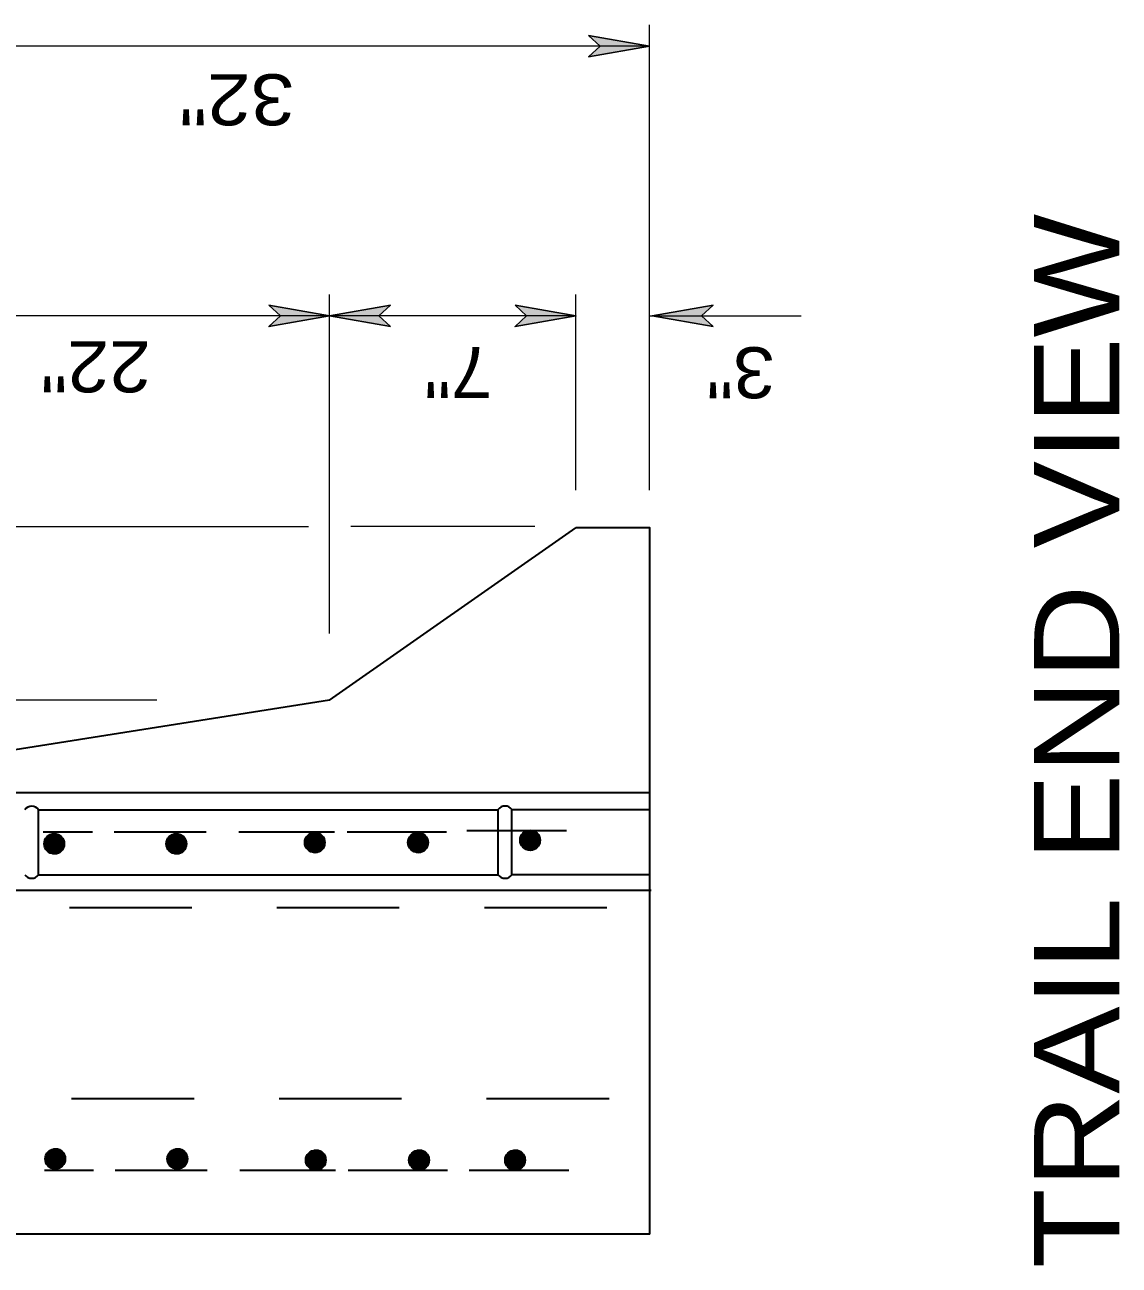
# Model space of a CAD drawing. Extents: x 12.6 to 19.5, y 6.1 to 16.3.
# Drawn here: x 15.643 to 16.93, y 14.328 to 15.785 of the extents above; entities that cross this region are included whole.
import ezdxf
from ezdxf.enums import TextEntityAlignment as Align

# ---------------------------------------------------------------- set-up
doc = ezdxf.new("R2010")
doc.units = 0
doc.header["$LTSCALE"] = 0.024
doc.linetypes.add('LONG_DASHED', pattern=[7.5, 6, -1.5])
for name, color, linetype, lineweight in [('1', 7, 'Continuous', 35), ('10', 7, 'Continuous', 25), ('12', 7, 'Continuous', 53)]:
    doc.layers.add(name, color=color, linetype=linetype, lineweight=lineweight)

msp = doc.modelspace()

# ---------------------------------------------------------------- hatches: boundary and pattern name
at = {"layer": '10'}
for points in [[(16.3056, 15.773), (16.3771, 15.7604), (16.3056, 15.7478), (16.3191, 15.7604)], [(15.9296, 15.4559), (16.0011, 15.4433), (15.9296, 15.4307), (15.9431, 15.4433)], [(16.0726, 15.4307), (16.0011, 15.4433), (16.0726, 15.4559), (16.0591, 15.4433)], [(16.2192, 15.4559), (16.2907, 15.4433), (16.2192, 15.4307), (16.2327, 15.4433)], [(16.4519, 15.4307), (16.3804, 15.4433), (16.4519, 15.4559), (16.4384, 15.4433)]]:
    msp.add_hatch(color=256, dxfattribs=at).paths.add_polyline_path(points)

# ---------------------------------------------------------------- linework, layer by layer
at = {"layer": '1'}
for p, q in [((16.0011, 14.9917), (16.2907, 15.1944)), ((16.0011, 14.9917), (15.4725, 14.9083)), ((15.451, 14.8831), (16.3776, 14.8831)), ((15.6588, 14.7865), (15.6588, 14.8628)), ((15.6588, 14.8628), (16.1991, 14.8628)), ((16.1991, 14.7865), (16.1991, 14.8631)), ((16.2154, 14.7865), (16.2154, 14.8631)), ((16.3776, 14.8628), (16.2154, 14.8628)), ((15.7221, 14.8364), (15.6644, 14.8364)), ((15.8557, 14.8364), (15.7477, 14.8364)), ((16.0068, 14.8364), (15.8943, 14.8364)), ((16.1385, 14.8364), (16.0215, 14.8364)), ((16.2795, 14.8381), (16.1625, 14.8381)), ((15.6588, 14.7865), (16.1991, 14.7865)), ((16.3776, 14.7865), (16.2154, 14.7865)), ((15.4524, 14.7686), (16.379, 14.7686)), ((15.7233, 14.439), (15.6656, 14.439)), ((15.8569, 14.439), (15.7489, 14.439)), ((16.008, 14.439), (15.8955, 14.439)), ((16.1397, 14.439), (16.0227, 14.439)), ((16.2822, 14.439), (16.1652, 14.439)), ((16.3776, 14.3643), (15.4755, 14.3643))]:
    msp.add_line(p, q, dxfattribs=at)
at = {"layer": '1', "linetype": 'LONG_DASHED'}
for p, q in [((15.451, 14.7481), (16.3747, 14.7481)), ((15.4537, 14.5235), (16.3774, 14.5235))]:
    msp.add_line(p, q, dxfattribs=at)
at = {"layer": '1'}
msp.add_lwpolyline([(16.3776, 14.3643), (16.3776, 15.1944), (16.2907, 15.1944)], dxfattribs=at)
for centre, radius in [((15.67718, 14.82296), 0.0118), ((15.67719, 14.82326), 0.01119), ((15.67744, 14.82292), 0.01108), ((15.67751, 14.8226), 0.01088), ((15.67778, 14.82196), 0.01098), ((15.67747, 14.82282), 0.01039), ((15.67768, 14.82265), 0.0102), ((15.67781, 14.8227), 0.00983), ((15.67795, 14.82241), 0.00973), ((15.67807, 14.82218), 0.0096), ((15.67822, 14.82187), 0.00955), ((15.67835, 14.82165), 0.00942), ((15.67805, 14.82201), 0.00878), ((15.67832, 14.82177), 0.00864), ((15.67884, 14.82214), 0.00846), ((15.67889, 14.82213), 0.00813), ((15.67872, 14.82214), 0.00759), ((15.67899, 14.82199), 0.00732), ((15.67911, 14.82199), 0.00717), ((15.67925, 14.82203), 0.00694), ((15.67904, 14.82181), 0.00626), ((15.67938, 14.82191), 0.00646), ((15.67903, 14.82165), 0.00587), ((15.67918, 14.82159), 0.0055), ((15.67926, 14.82157), 0.00503), ((15.6793, 14.82157), 0.00469), ((15.67933, 14.82138), 0.00456), ((15.6796, 14.82149), 0.00466), ((15.67952, 14.82143), 0.0042), ((15.67958, 14.82135), 0.0039), ((15.82077, 14.82296), 0.0118), ((15.82078, 14.82326), 0.01119), ((15.82103, 14.82292), 0.01108), ((15.8211, 14.8226), 0.01088), ((15.82137, 14.82196), 0.01098), ((15.82106, 14.82282), 0.01039), ((15.82126, 14.82265), 0.0102), ((15.8214, 14.8227), 0.00983), ((15.82153, 14.82241), 0.00973), ((15.82165, 14.82218), 0.0096), ((15.8218, 14.82187), 0.00955), ((15.82194, 14.82165), 0.00942), ((15.82164, 14.82201), 0.00878), ((15.82191, 14.82177), 0.00864), ((15.82243, 14.82214), 0.00846), ((15.82248, 14.82213), 0.00813), ((15.82231, 14.82214), 0.00759), ((15.82258, 14.82199), 0.00732), ((15.8227, 14.82199), 0.00717), ((15.82283, 14.82203), 0.00694), ((15.82263, 14.82181), 0.00626), ((15.82297, 14.82191), 0.00646), ((15.82261, 14.82165), 0.00587), ((15.82277, 14.82159), 0.0055), ((15.82285, 14.82157), 0.00503), ((15.82288, 14.82157), 0.00469), ((15.82292, 14.82138), 0.00456), ((15.82319, 14.82149), 0.00466), ((15.8231, 14.82143), 0.0042), ((15.82317, 14.82135), 0.0039), ((15.98359, 14.82446), 0.0118), ((15.9836, 14.82476), 0.01119), ((15.98385, 14.82442), 0.01108), ((15.98392, 14.8241), 0.01088), ((15.98419, 14.82346), 0.01098), ((15.98389, 14.82432), 0.01039), ((15.98409, 14.82415), 0.0102), ((15.98422, 14.8242), 0.00983), ((15.98436, 14.82391), 0.00973), ((15.98448, 14.82368), 0.0096), ((15.98463, 14.82337), 0.00955), ((15.98476, 14.82315), 0.00942), ((15.98446, 14.82351), 0.00878), ((15.98473, 14.82327), 0.00864), ((15.98525, 14.82364), 0.00846), ((15.9853, 14.82363), 0.00813), ((15.98514, 14.82364), 0.00759), ((15.98541, 14.82349), 0.00732), ((15.98552, 14.82349), 0.00717), ((15.98566, 14.82353), 0.00694), ((15.98546, 14.82331), 0.00626), ((15.98579, 14.82341), 0.00646), ((15.98544, 14.82315), 0.00587), ((15.98559, 14.82309), 0.0055), ((15.98568, 14.82307), 0.00503), ((15.98571, 14.82307), 0.00469), ((15.98574, 14.82288), 0.00456), ((15.98601, 14.82299), 0.00466), ((15.98593, 14.82293), 0.0042), ((15.986, 14.82285), 0.0039), ((15.98601, 14.82277), 0.00365), ((15.98595, 14.82288), 0.00348), ((15.98598, 14.82272), 0.00314), ((15.98603, 14.82277), 0.00286), ((15.9863, 14.82268), 0.00275), ((15.98623, 14.82282), 0.00252), ((16.10498, 14.82446), 0.0118), ((16.10499, 14.82476), 0.01119), ((16.10524, 14.82442), 0.01108), ((16.10531, 14.8241), 0.01088), ((16.10558, 14.82346), 0.01098), ((16.10527, 14.82432), 0.01039), ((16.10548, 14.82415), 0.0102), ((16.10561, 14.8242), 0.00983), ((16.10575, 14.82391), 0.00973), ((16.10587, 14.82368), 0.0096), ((16.10602, 14.82337), 0.00955), ((16.10615, 14.82315), 0.00942), ((16.10585, 14.82351), 0.00878), ((16.10612, 14.82327), 0.00864), ((16.10664, 14.82364), 0.00846), ((16.10669, 14.82363), 0.00813), ((16.10652, 14.82364), 0.00759), ((16.10679, 14.82349), 0.00732), ((16.10691, 14.82349), 0.00717), ((16.10705, 14.82353), 0.00694), ((16.10684, 14.82331), 0.00626), ((16.10718, 14.82341), 0.00646), ((16.10683, 14.82315), 0.00587), ((16.10698, 14.82309), 0.0055), ((16.10706, 14.82307), 0.00503), ((16.1071, 14.82307), 0.00469), ((16.10713, 14.82288), 0.00456), ((16.1074, 14.82299), 0.00466), ((16.10732, 14.82293), 0.0042), ((16.10738, 14.82285), 0.0039), ((16.1074, 14.82277), 0.00365), ((16.10733, 14.82288), 0.00348), ((16.10737, 14.82272), 0.00314), ((16.10742, 14.82277), 0.00286), ((16.10769, 14.82268), 0.00275), ((16.10762, 14.82282), 0.00252), ((16.23672, 14.82716), 0.0118), ((16.23673, 14.82746), 0.01119), ((16.23698, 14.82712), 0.01108), ((16.23705, 14.8268), 0.01088), ((16.23732, 14.82616), 0.01098), ((16.23701, 14.82702), 0.01039), ((16.23721, 14.82685), 0.0102), ((16.23735, 14.8269), 0.00983), ((16.23748, 14.82661), 0.00973), ((16.2376, 14.82638), 0.0096), ((16.23775, 14.82607), 0.00955), ((16.23789, 14.82585), 0.00942), ((16.23759, 14.82621), 0.00878), ((16.23786, 14.82597), 0.00864), ((16.23838, 14.82634), 0.00846), ((16.23843, 14.82633), 0.00813), ((16.23826, 14.82634), 0.00759), ((16.23853, 14.82619), 0.00732), ((16.23865, 14.82619), 0.00717), ((16.23878, 14.82623), 0.00694), ((16.23858, 14.82601), 0.00626), ((16.23892, 14.82611), 0.00646), ((16.23856, 14.82585), 0.00587), ((16.23872, 14.82579), 0.0055), ((16.2388, 14.82577), 0.00503), ((16.23883, 14.82577), 0.00469), ((16.23887, 14.82558), 0.00456), ((16.23914, 14.82569), 0.00466), ((16.23905, 14.82563), 0.0042), ((16.23912, 14.82555), 0.0039), ((16.23914, 14.82547), 0.00365), ((16.23907, 14.82558), 0.00348), ((16.2391, 14.82542), 0.00314), ((16.23916, 14.82547), 0.00286), ((16.23943, 14.82538), 0.00275), ((16.23936, 14.82552), 0.00252), ((16.23916, 14.82542), 0.00208), ((16.23924, 14.82536), 0.00199), ((16.2389, 14.82531), 0.00142), ((16.23968, 14.8253), 0.00219), ((16.23927, 14.82533), 0.00155), ((16.23899, 14.82531), 0.000996), ((16.23943, 14.8253), 0.00127), ((16.23905, 14.82533), 0.000827), ((16.23921, 14.82523), 0.000776), ((16.23922, 14.82535), 0.000456), ((15.6796, 14.82127), 0.00365), ((15.67953, 14.82138), 0.00348), ((15.67957, 14.82122), 0.00314), ((15.67962, 14.82127), 0.00286), ((15.67989, 14.82118), 0.00275), ((15.67982, 14.82132), 0.00252), ((15.67962, 14.82122), 0.00208), ((15.6797, 14.82116), 0.00199), ((15.67936, 14.82111), 0.00142), ((15.68014, 14.8211), 0.00219), ((15.67974, 14.82113), 0.00155), ((15.67945, 14.82111), 0.000996), ((15.67989, 14.8211), 0.00127), ((15.67952, 14.82113), 0.000827), ((15.67967, 14.82103), 0.000776), ((15.67969, 14.82115), 0.000456), ((15.82319, 14.82127), 0.00365), ((15.82312, 14.82138), 0.00348), ((15.82315, 14.82122), 0.00314), ((15.82321, 14.82127), 0.00286), ((15.82348, 14.82118), 0.00275), ((15.82341, 14.82132), 0.00252), ((15.82321, 14.82122), 0.00208), ((15.82329, 14.82116), 0.00199), ((15.82295, 14.82111), 0.00142), ((15.82373, 14.8211), 0.00219), ((15.82332, 14.82113), 0.00155), ((15.82304, 14.82111), 0.000996), ((15.82348, 14.8211), 0.00127), ((15.8231, 14.82113), 0.000827), ((15.82326, 14.82103), 0.000776), ((15.82327, 14.82115), 0.000456), ((15.98603, 14.82272), 0.00208), ((15.98611, 14.82266), 0.00199), ((15.98655, 14.8226), 0.00219), ((15.98578, 14.82261), 0.00142), ((15.98615, 14.82263), 0.00155), ((15.98586, 14.82261), 0.000996), ((15.9863, 14.8226), 0.00127), ((15.98593, 14.82263), 0.000827), ((15.98608, 14.82253), 0.000776), ((15.9861, 14.82265), 0.000456), ((16.10742, 14.82272), 0.00208), ((16.1075, 14.82266), 0.00199), ((16.10716, 14.82261), 0.00142), ((16.10794, 14.8226), 0.00219), ((16.10754, 14.82263), 0.00155), ((16.10725, 14.82261), 0.000996), ((16.10769, 14.8226), 0.00127), ((16.10732, 14.82263), 0.000827), ((16.10747, 14.82253), 0.000776), ((16.10749, 14.82265), 0.000456), ((15.67838, 14.45254), 0.0118), ((15.67839, 14.45225), 0.01119), ((15.67864, 14.45259), 0.01108), ((15.67871, 14.45291), 0.01088), ((15.67898, 14.45355), 0.01098), ((15.67867, 14.45269), 0.01039), ((15.67888, 14.45286), 0.0102), ((15.67901, 14.45281), 0.00983), ((15.67915, 14.45309), 0.00973), ((15.67927, 14.45333), 0.0096), ((15.67942, 14.45363), 0.00955), ((15.67955, 14.45385), 0.00942), ((15.67925, 14.4535), 0.00878), ((15.67952, 14.45374), 0.00864), ((15.68004, 14.45336), 0.00846), ((15.68009, 14.45338), 0.00813), ((15.67992, 14.45336), 0.00759), ((15.68019, 14.45352), 0.00732), ((15.68031, 14.45352), 0.00717), ((15.82197, 14.45254), 0.0118), ((15.82198, 14.45225), 0.01119), ((15.82223, 14.45259), 0.01108), ((15.8223, 14.45291), 0.01088), ((15.82257, 14.45355), 0.01098), ((15.82226, 14.45269), 0.01039), ((15.82246, 14.45286), 0.0102), ((15.8226, 14.45281), 0.00983), ((15.82273, 14.45309), 0.00973), ((15.82285, 14.45333), 0.0096), ((15.823, 14.45363), 0.00955), ((15.82314, 14.45385), 0.00942), ((15.82284, 14.4535), 0.00878), ((15.82311, 14.45374), 0.00864), ((15.82363, 14.45336), 0.00846), ((15.82368, 14.45338), 0.00813), ((15.82351, 14.45336), 0.00759), ((15.82378, 14.45352), 0.00732), ((15.8239, 14.45352), 0.00717), ((15.98479, 14.45104), 0.0118), ((15.9848, 14.45075), 0.01119), ((15.98505, 14.45109), 0.01108), ((15.98512, 14.45141), 0.01088), ((15.98539, 14.45205), 0.01098), ((15.98509, 14.45119), 0.01039), ((15.98529, 14.45136), 0.0102), ((15.98542, 14.45131), 0.00983), ((15.98556, 14.45159), 0.00973), ((15.98568, 14.45183), 0.0096), ((15.98583, 14.45213), 0.00955), ((15.98596, 14.45235), 0.00942), ((15.98566, 14.452), 0.00878), ((15.98593, 14.45224), 0.00864), ((16.10618, 14.45104), 0.0118), ((16.10619, 14.45075), 0.01119), ((16.10644, 14.45109), 0.01108), ((16.10651, 14.45141), 0.01088), ((16.10678, 14.45205), 0.01098), ((16.10647, 14.45119), 0.01039), ((16.10668, 14.45136), 0.0102), ((16.10681, 14.45131), 0.00983), ((16.10695, 14.45159), 0.00973), ((16.10707, 14.45183), 0.0096), ((16.10722, 14.45213), 0.00955), ((16.10735, 14.45235), 0.00942), ((16.10705, 14.452), 0.00878), ((16.10732, 14.45224), 0.00864), ((16.21909, 14.45104), 0.0118), ((16.2191, 14.45075), 0.01119), ((16.21935, 14.45109), 0.01108), ((16.21942, 14.45141), 0.01088), ((16.21969, 14.45205), 0.01098), ((16.21939, 14.45119), 0.01039), ((16.21959, 14.45136), 0.0102), ((16.21972, 14.45131), 0.00983), ((16.21986, 14.45159), 0.00973), ((16.21998, 14.45183), 0.0096), ((16.22013, 14.45213), 0.00955), ((16.22026, 14.45235), 0.00942), ((16.21996, 14.452), 0.00878), ((16.22023, 14.45224), 0.00864), ((15.68045, 14.45348), 0.00694), ((15.68024, 14.4537), 0.00626), ((15.68058, 14.4536), 0.00646), ((15.68023, 14.45385), 0.00587), ((15.68038, 14.45392), 0.0055), ((15.68046, 14.45394), 0.00503), ((15.6805, 14.45394), 0.00469), ((15.68053, 14.45412), 0.00456), ((15.6808, 14.45402), 0.00466), ((15.68072, 14.45407), 0.0042), ((15.68078, 14.45416), 0.0039), ((15.6808, 14.45424), 0.00365), ((15.68073, 14.45412), 0.00348), ((15.68077, 14.45429), 0.00314), ((15.68082, 14.45424), 0.00286), ((15.68109, 14.45433), 0.00275), ((15.68102, 14.45419), 0.00252), ((15.68082, 14.45429), 0.00208), ((15.6809, 14.45434), 0.00199), ((15.68056, 14.45439), 0.00142), ((15.68134, 14.45441), 0.00219), ((15.68094, 14.45438), 0.00155), ((15.68065, 14.45439), 0.000996), ((15.68109, 14.45441), 0.00127), ((15.68072, 14.45438), 0.000827), ((15.68087, 14.45448), 0.000776), ((15.68089, 14.45436), 0.000456), ((15.82403, 14.45348), 0.00694), ((15.82383, 14.4537), 0.00626), ((15.82417, 14.4536), 0.00646), ((15.82381, 14.45385), 0.00587), ((15.82397, 14.45392), 0.0055), ((15.82405, 14.45394), 0.00503), ((15.82408, 14.45394), 0.00469), ((15.82412, 14.45412), 0.00456), ((15.82439, 14.45402), 0.00466), ((15.8243, 14.45407), 0.0042), ((15.82437, 14.45416), 0.0039), ((15.82439, 14.45424), 0.00365), ((15.82432, 14.45412), 0.00348), ((15.82435, 14.45429), 0.00314), ((15.82441, 14.45424), 0.00286), ((15.82468, 14.45433), 0.00275), ((15.82461, 14.45419), 0.00252), ((15.82441, 14.45429), 0.00208), ((15.82449, 14.45434), 0.00199), ((15.82415, 14.45439), 0.00142), ((15.82493, 14.45441), 0.00219), ((15.82452, 14.45438), 0.00155), ((15.82424, 14.45439), 0.000996), ((15.82468, 14.45441), 0.00127), ((15.8243, 14.45438), 0.000827), ((15.82446, 14.45448), 0.000776), ((15.82447, 14.45436), 0.000456), ((15.98645, 14.45186), 0.00846), ((15.9865, 14.45188), 0.00813), ((15.98634, 14.45186), 0.00759), ((15.98661, 14.45202), 0.00732), ((15.98672, 14.45202), 0.00717), ((15.98686, 14.45198), 0.00694), ((15.98666, 14.4522), 0.00626), ((15.98699, 14.4521), 0.00646), ((15.98664, 14.45235), 0.00587), ((15.98679, 14.45242), 0.0055), ((15.98688, 14.45244), 0.00503), ((15.98691, 14.45244), 0.00469), ((15.98694, 14.45262), 0.00456), ((15.98721, 14.45252), 0.00466), ((15.98713, 14.45257), 0.0042), ((15.9872, 14.45266), 0.0039), ((15.98721, 14.45274), 0.00365), ((15.98715, 14.45262), 0.00348), ((15.98718, 14.45279), 0.00314), ((15.98723, 14.45274), 0.00286), ((15.9875, 14.45283), 0.00275), ((15.98743, 14.45269), 0.00252), ((15.98723, 14.45279), 0.00208), ((15.98731, 14.45284), 0.00199), ((15.98775, 14.45291), 0.00219), ((15.98698, 14.45289), 0.00142), ((15.98735, 14.45288), 0.00155), ((15.98706, 14.45289), 0.000996), ((15.9875, 14.45291), 0.00127), ((15.98713, 14.45288), 0.000827), ((15.98728, 14.45298), 0.000776), ((15.9873, 14.45286), 0.000456), ((16.10784, 14.45186), 0.00846), ((16.10789, 14.45188), 0.00813), ((16.10772, 14.45186), 0.00759), ((16.10799, 14.45202), 0.00732), ((16.10811, 14.45202), 0.00717), ((16.10825, 14.45198), 0.00694), ((16.10804, 14.4522), 0.00626), ((16.10838, 14.4521), 0.00646), ((16.10803, 14.45235), 0.00587), ((16.10818, 14.45242), 0.0055), ((16.10826, 14.45244), 0.00503), ((16.1083, 14.45244), 0.00469), ((16.10833, 14.45262), 0.00456), ((16.1086, 14.45252), 0.00466), ((16.10852, 14.45257), 0.0042), ((16.10858, 14.45266), 0.0039), ((16.1086, 14.45274), 0.00365), ((16.10853, 14.45262), 0.00348), ((16.10857, 14.45279), 0.00314), ((16.10862, 14.45274), 0.00286), ((16.10889, 14.45283), 0.00275), ((16.10882, 14.45269), 0.00252), ((16.10862, 14.45279), 0.00208), ((16.1087, 14.45284), 0.00199), ((16.10836, 14.45289), 0.00142), ((16.10914, 14.45291), 0.00219), ((16.10874, 14.45288), 0.00155), ((16.10845, 14.45289), 0.000996), ((16.10889, 14.45291), 0.00127), ((16.10852, 14.45288), 0.000827), ((16.10867, 14.45298), 0.000776), ((16.10869, 14.45286), 0.000456), ((16.22075, 14.45186), 0.00846), ((16.2208, 14.45188), 0.00813), ((16.22064, 14.45186), 0.00759), ((16.22091, 14.45202), 0.00732), ((16.22102, 14.45202), 0.00717), ((16.22116, 14.45198), 0.00694), ((16.22096, 14.4522), 0.00626), ((16.22129, 14.4521), 0.00646), ((16.22094, 14.45235), 0.00587), ((16.22109, 14.45242), 0.0055), ((16.22118, 14.45244), 0.00503), ((16.22121, 14.45244), 0.00469), ((16.22124, 14.45262), 0.00456), ((16.22151, 14.45252), 0.00466), ((16.22143, 14.45257), 0.0042), ((16.2215, 14.45266), 0.0039), ((16.22151, 14.45274), 0.00365), ((16.22145, 14.45262), 0.00348), ((16.22148, 14.45279), 0.00314), ((16.22153, 14.45274), 0.00286), ((16.2218, 14.45283), 0.00275), ((16.22173, 14.45269), 0.00252), ((16.22153, 14.45279), 0.00208), ((16.22161, 14.45284), 0.00199), ((16.22205, 14.45291), 0.00219), ((16.22128, 14.45289), 0.00142), ((16.22165, 14.45288), 0.00155), ((16.22136, 14.45289), 0.000996), ((16.2218, 14.45291), 0.00127), ((16.22143, 14.45288), 0.000827), ((16.22158, 14.45298), 0.000776), ((16.2216, 14.45286), 0.000456)]:
    msp.add_circle(centre, radius, dxfattribs=at)
for centre, start, end in [((15.65076, 14.85699), 35.9422, 144.05781), ((16.20734, 14.85721), 35.9422, 144.05781), ((15.65076, 14.7924), 215.94219, 324.0578), ((16.20734, 14.7924), 215.94219, 324.0578)]:
    msp.add_arc(centre, 0.01005, start, end, dxfattribs=at)
at = {"layer": '10'}
for p, q in [((16.3771, 15.7604), (16.3056, 15.773)), ((16.3771, 15.7604), (16.3056, 15.7478)), ((16.0011, 15.4433), (15.9296, 15.4559)), ((16.0011, 15.4433), (16.0726, 15.4559)), ((16.2907, 15.4433), (16.2192, 15.4559)), ((16.3804, 15.4433), (16.4519, 15.4559)), ((16.0011, 15.4433), (15.9296, 15.4307)), ((16.0011, 15.4433), (16.0726, 15.4307)), ((16.2907, 15.4433), (16.2192, 15.4307)), ((16.3804, 15.4433), (16.4519, 15.4307))]:
    msp.add_line(p, q, dxfattribs=at)
at = {"layer": '10', "lineweight": 13}
for p, q in [((16.3771, 15.2386), (16.3771, 15.7854)), ((16.3771, 15.7604), (15.4524, 15.7604)), ((16.0011, 15.0701), (16.0011, 15.4683)), ((16.2907, 15.2386), (16.2907, 15.4683)), ((16.3771, 15.4433), (16.5556, 15.4433)), ((14.9436, 15.1957), (15.9761, 15.1957)), ((16.2422, 15.1957), (16.0261, 15.1957)), ((15.7979, 14.9917), (15.4774, 14.9917))]:
    msp.add_line(p, q, dxfattribs=at)
at = {"layer": '10'}
for points in [[(16.3056, 15.773), (16.3191, 15.7604), (16.3056, 15.7478)], [(15.9296, 15.4559), (15.9431, 15.4433), (15.9296, 15.4307)], [(16.0726, 15.4307), (16.0591, 15.4433), (16.0726, 15.4559)], [(16.2192, 15.4559), (16.2327, 15.4433), (16.2192, 15.4307)], [(16.4519, 15.4307), (16.4384, 15.4433), (16.4519, 15.4559)]]:
    msp.add_lwpolyline(points, dxfattribs=at)
for points in [[(16.3056, 15.773), (16.3771, 15.7604), (16.3056, 15.7478), (16.3191, 15.7604)], [(15.9296, 15.4559), (16.0011, 15.4433), (15.9296, 15.4307), (15.9431, 15.4433)], [(16.0726, 15.4307), (16.0011, 15.4433), (16.0726, 15.4559), (16.0591, 15.4433)], [(16.2192, 15.4559), (16.2907, 15.4433), (16.2192, 15.4307), (16.2327, 15.4433)], [(16.4519, 15.4307), (16.3804, 15.4433), (16.4519, 15.4559), (16.4384, 15.4433)]]:
    msp.add_lwpolyline(points, close=True, dxfattribs=at)
at = {"layer": '10', "lineweight": 13}
msp.add_lwpolyline([(16.2907, 15.4433), (16.0011, 15.4433), (15.4524, 15.4433)], dxfattribs=at)

# ---------------------------------------------------------------- texts
at = {"layer": '12'}
for s, width, p in [('32"', 1.15, (15.9596, 15.7273)), ('22"', 1.1, (15.7908, 15.4135)), ('7"', 1.1, (16.1927, 15.4069)), ('3"', 1.1, (16.5246, 15.4065))]:
    msp.add_text(s, height=0.06, rotation=180, dxfattribs=dict(at, width=width)).set_placement(p)
at = {"layer": '12', "width": 1.15}
msp.add_text('TRAIL END VIEW', height=0.1, rotation=90, dxfattribs=at).set_placement((16.9295, 14.9437), align=Align.CENTER)

doc.saveas('drawing.dxf')
